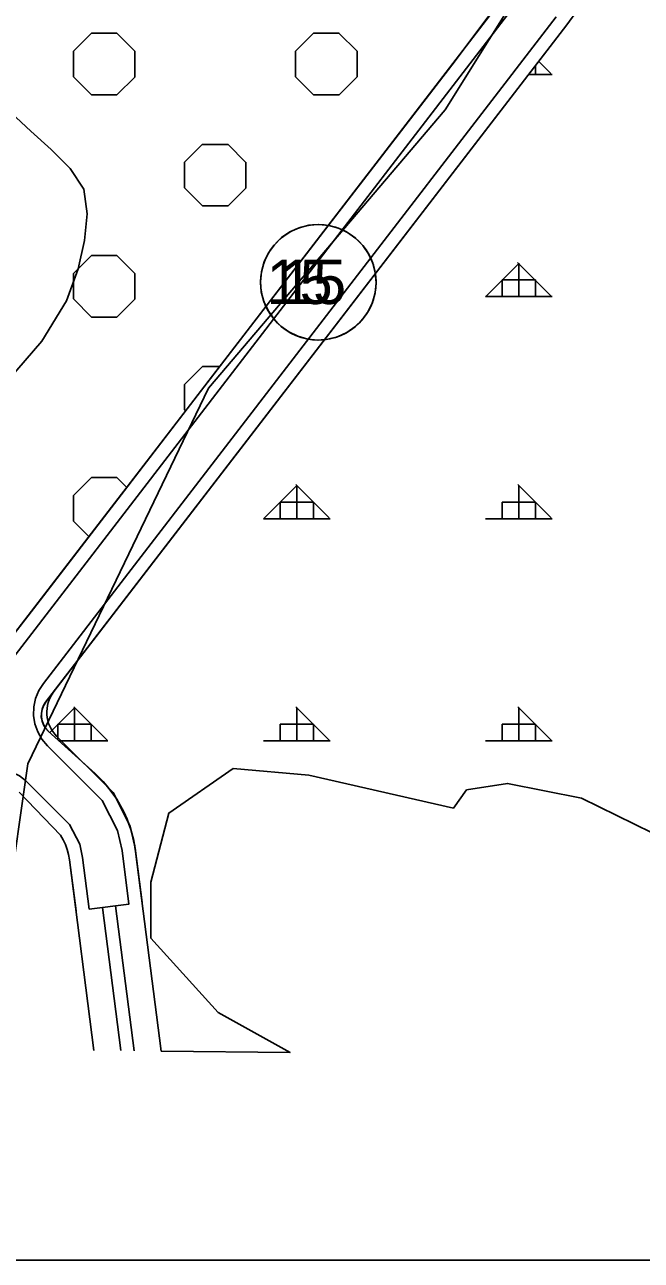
# Model space of a CAD drawing. Extents: x 410727 to 412947, y 4463506 to 4466382.
# Drawn here: x 410893.4 to 411032.2, y 4463506.2 to 4463784.3 of the extents above; entities that cross this region are included whole.
import ezdxf

# ---------------------------------------------------------------- set-up
doc = ezdxf.new("R2010")
doc.units = 0
for name, color, linetype in [('ADAKENARI', 7, 'Continuous'), ('F_ADAKENARI', 7, 'Continuous'), ('KALDIRIM', 7, 'Continuous'), ('LJ_ÇERÇEVE', 7, 'Continuous'), ('PL_AYA_AGACLANDIRIL', 7, 'Continuous'), ('PL_AYA_ORMAN', 7, 'Continuous'), ('SM_BEYAZ', 7, 'Continuous'), ('SM_DAİRE', 7, 'Continuous'), ('sm_yol_beyaz', 7, 'Continuous'), ('sm_yol_genisligi', 7, 'Continuous'), ('SM_YOLGEN', 7, 'Continuous'), ('TR_AGACLANDIRILACAK', 7, 'Continuous'), ('TR_ORMAN', 7, 'Continuous'), ('Yerlesime_uygunluk_sınırı', 7, 'Continuous')]:
    doc.layers.add(name, color=color, linetype=linetype)

msp = doc.modelspace()

# ---------------------------------------------------------------- linework, layer by layer
at = {"layer": 'ADAKENARI'}
for p, q in [((410998.01, 4463786.26), (410888.18, 4463643.49)), ((410898.1, 4463631.77), (411015.41, 4463784.28)), ((410899.96, 4463634.19), (411015.41, 4463784.28)), ((410909.24, 4463615.7), (410898.67, 4463625.3)), ((410913.31, 4463611.43), (410900.62, 4463624.08)), ((410940.29, 4463616.85), (410925.86, 4463606.84)), ((410957.32, 4463615.37), (410940.29, 4463616.85)), ((410989.89, 4463607.95), (410957.32, 4463615.37)), ((410992.85, 4463612.03), (410989.89, 4463607.95)), ((411002.1, 4463613.51), (410992.85, 4463612.03)), ((411018.76, 4463610.18), (411002.1, 4463613.51)), ((410917.14, 4463603.89), (410913.31, 4463611.43)), ((411034.67, 4463602.39), (411018.76, 4463610.18)), ((410925.86, 4463606.84), (410921.79, 4463591.26)), ((410918.26, 4463598.9), (410917.14, 4463603.89)), ((410919.82, 4463586.73), (410918.26, 4463598.9)), ((410924.1, 4463553.24), (410918.35, 4463598.21)), ((410903.47, 4463596.3), (410904.94, 4463584.83)), ((410921.79, 4463591.26), (410921.79, 4463578.65)), ((410921.79, 4463578.65), (410936.96, 4463561.96)), ((410921.79, 4463578.65), (410936.96, 4463561.96)), ((410936.96, 4463561.96), (410953.14, 4463552.9))]:
    msp.add_line(p, q, dxfattribs=at)
for centre, radius, start, end in [((410906.03, 4463629.51), 7.67, 142.4314, 225.1023), ((410901.9, 4463628.85), 4.79, 142.4314, 227.7263), ((410901.9, 4463628.85), 4.79, 142.4314, 227.7263), ((410890.04, 4463594.59), 28.53, 7.289, 47.7263), ((410890.04, 4463594.59), 28.53, 7.289, 47.7263)]:
    msp.add_arc(centre, radius, start, end, dxfattribs=at)
at = {"layer": 'F_ADAKENARI'}
for p, q in [((410898.1, 4463631.77), (411015.41, 4463784.28)), ((410997.92, 4463786.32), (410989.51, 4463775.21)), ((410989.51, 4463775.21), (410935.69, 4463705.24)), ((410935.69, 4463705.24), (410915.86, 4463679.46)), ((410915.86, 4463679.46), (410895.37, 4463652.83)), ((410895.37, 4463652.83), (410888.19, 4463643.49)), ((410898.1, 4463631.77), (410897.62, 4463631.02)), ((410897.13, 4463629.32), (410897.12, 4463628.43)), ((410897.12, 4463628.43), (410897.29, 4463627.55)), ((410897.3, 4463630.19), (410897.13, 4463629.32)), ((410897.62, 4463631.02), (410897.3, 4463630.19)), ((410897.29, 4463627.55), (410897.61, 4463626.72)), ((410897.61, 4463626.72), (410898.07, 4463625.96)), ((410898.07, 4463625.96), (410898.67, 4463625.3)), ((410909.24, 4463615.7), (410898.67, 4463625.3)), ((410911.02, 4463613.93), (410909.24, 4463615.7)), ((410912.65, 4463612), (410911.02, 4463613.93)), ((410914.09, 4463609.94), (410912.65, 4463612)), ((410901.45, 4463601.87), (410892.1, 4463611.52)), ((410915.35, 4463607.77), (410914.09, 4463609.94)), ((410916.42, 4463605.48), (410915.35, 4463607.77)), ((410917.27, 4463603.12), (410916.42, 4463605.48)), ((410902.05, 4463600.84), (410901.45, 4463601.87)), ((410902.55, 4463599.76), (410902.05, 4463600.84)), ((410917.92, 4463600.69), (410917.27, 4463603.12)), ((410918.35, 4463598.21), (410917.92, 4463600.69)), ((410902.96, 4463598.63), (410902.55, 4463599.76)), ((410903.27, 4463597.48), (410902.96, 4463598.63)), ((410924.1, 4463553.24), (410918.35, 4463598.21)), ((410903.47, 4463596.3), (410903.27, 4463597.48)), ((410903.47, 4463596.3), (410908.95, 4463553.42))]:
    msp.add_line(p, q, dxfattribs=at)
at = {"layer": 'KALDIRIM'}
for p, q in [((410915.01, 4463553.35), (410910.89, 4463585.59)), ((410918.04, 4463553.31), (410913.86, 4463585.97))]:
    msp.add_line(p, q, dxfattribs=at)
for points in [[(410869.51, 4463620.34), (410870.81, 4463620.5), (410872.09, 4463620.82), (410873.32, 4463621.3), (410874.48, 4463621.92), (410875.55, 4463622.67), (410876.53, 4463623.55), (410877.4, 4463624.54), (411005.8, 4463791.46)], [(411013.01, 4463786.08), (410897.58, 4463636.01), (410896.55, 4463634.39), (410895.83, 4463632.61), (410895.43, 4463630.73), (410895.39, 4463628.81), (410895.69, 4463626.91), (410896.32, 4463625.1), (410897.27, 4463623.43), (410898.5, 4463621.95), (410910.85, 4463609.64), (410914.29, 4463602.87), (410915.3, 4463598.38), (410916.84, 4463586.35), (410907.91, 4463585.21), (410906.43, 4463596.82), (410905.76, 4463599.8), (410903.48, 4463604.29), (410893.55, 4463614.18)], [(410893.55, 4463614.18), (410892.2, 4463615.24), (410890.63, 4463615.94), (410888.94, 4463616.25), (410887.23, 4463616.15), (410885.59, 4463615.63), (410884.12, 4463614.75), (410882.91, 4463613.53), (410882.02, 4463612.06), (410855.88, 4463554.04)]]:
    msp.add_lwpolyline(points, dxfattribs=at)
at = {"layer": 'LJ_ÇERÇEVE'}
msp.add_lwpolyline([(410732.32, 4466381.6), (412946.74, 4466381.6), (412946.74, 4463506.16), (410732.32, 4463506.16)], close=True, dxfattribs=at)
at = {"layer": 'PL_AYA_AGACLANDIRIL'}
msp.add_lwpolyline([(410768.78, 4463916.77), (410766.18, 4463697.48), (410777.91, 4463692.29), (410788.9, 4463688.62), (410805.39, 4463682.42), (410820.27, 4463677.15), (410829.43, 4463674.39), (410842.25, 4463668.64), (410849.8, 4463665.2), (410858.96, 4463661.3), (410863.08, 4463657.85), (410871.02, 4463653.05), (410882.92, 4463646.63), (410888.18, 4463643.49), (410998.01, 4463786.26)], dxfattribs=at)
at = {"layer": 'PL_AYA_ORMAN'}
for points in [[(411018.08, 4463787.85), (411015.41, 4463784.28), (410898.1, 4463631.77), (410897.62, 4463631.02), (410897.3, 4463630.19), (410897.13, 4463629.32), (410897.12, 4463628.43), (410897.29, 4463627.55), (410897.61, 4463626.72), (410898.07, 4463625.96), (410898.67, 4463625.3), (410909.24, 4463615.7), (410911.02, 4463613.93), (410912.65, 4463612), (410914.09, 4463609.94), (410915.35, 4463607.77), (410916.42, 4463605.48), (410917.27, 4463603.12), (410917.92, 4463600.69), (410918.35, 4463598.21), (410924.1, 4463553.24)], [(410924.1, 4463553.24), (410953.14, 4463552.9), (410936.96, 4463561.96), (410921.79, 4463578.65), (410921.79, 4463591.26), (410925.86, 4463606.84), (410940.29, 4463616.85), (410957.32, 4463615.37), (410989.89, 4463607.95), (410992.85, 4463612.03), (411002.1, 4463613.51), (411018.76, 4463610.18), (411034.67, 4463602.39), (411057.99, 4463584.96), (411067.25, 4463601.65), (411078.72, 4463599.05), (411105, 4463582.73), (411130.91, 4463564.19), (411151.28, 4463550.58), (411512.89, 4463546.35)]]:
    msp.add_lwpolyline(points, dxfattribs=at)
at = {"layer": 'SM_BEYAZ'}
for start, end in [(0, 180), (180, 0)]:
    msp.add_arc((410959.48, 4463726.31), 13, start, end, dxfattribs=at)
at = {"layer": 'SM_DAİRE'}
msp.add_lwpolyline([(410972.48, 4463726.18), (410972.26, 4463723.93), (410971.65, 4463721.74), (410970.67, 4463719.7), (410969.35, 4463717.86), (410967.74, 4463716.27), (410965.87, 4463714.99), (410963.8, 4463714.05), (410961.61, 4463713.48), (410959.35, 4463713.31), (410957.09, 4463713.53), (410954.91, 4463714.14), (410952.87, 4463715.12), (410951.02, 4463716.43), (410949.44, 4463718.05), (410948.16, 4463719.92), (410947.22, 4463721.98), (410946.65, 4463724.18), (410946.48, 4463726.44), (410946.7, 4463728.69), (410947.31, 4463730.88), (410948.28, 4463732.92), (410949.6, 4463734.76), (410951.22, 4463736.35), (410953.09, 4463737.63), (410955.15, 4463738.57), (410957.35, 4463739.13), (410959.61, 4463739.31), (410961.86, 4463739.09), (410964.04, 4463738.48), (410966.09, 4463737.5), (410967.93, 4463736.19), (410969.52, 4463734.57), (410970.8, 4463732.7), (410971.74, 4463730.63), (410972.3, 4463728.44), (410972.48, 4463726.18)], dxfattribs=at)
msp.add_lwpolyline([(410972.48, 4463726.18), (410972.26, 4463723.93), (410971.65, 4463721.74), (410970.67, 4463719.7), (410969.35, 4463717.86), (410967.74, 4463716.27), (410965.87, 4463714.99), (410963.8, 4463714.05), (410961.61, 4463713.48), (410959.35, 4463713.31), (410957.09, 4463713.53), (410954.91, 4463714.14), (410952.87, 4463715.12), (410951.02, 4463716.43), (410949.44, 4463718.05), (410948.16, 4463719.92), (410947.22, 4463721.98), (410946.65, 4463724.18), (410946.48, 4463726.44), (410946.7, 4463728.69), (410947.31, 4463730.88), (410948.28, 4463732.92), (410949.6, 4463734.76), (410951.22, 4463736.35), (410953.09, 4463737.63), (410955.15, 4463738.57), (410957.35, 4463739.13), (410959.61, 4463739.31), (410961.86, 4463739.09), (410964.04, 4463738.48), (410966.09, 4463737.5), (410967.93, 4463736.19), (410969.52, 4463734.57), (410970.8, 4463732.7), (410971.74, 4463730.63), (410972.3, 4463728.44), (410972.48, 4463726.18)], dxfattribs=at)
at = {"layer": 'sm_yol_beyaz'}
msp.add_lwpolyline([(410972.48, 4463726.18), (410972.3, 4463728.44), (410971.74, 4463730.63), (410970.8, 4463732.7), (410969.52, 4463734.57), (410967.93, 4463736.19), (410966.09, 4463737.5), (410964.04, 4463738.48), (410961.86, 4463739.09), (410959.61, 4463739.31), (410957.35, 4463739.13), (410955.15, 4463738.57), (410953.09, 4463737.63), (410951.22, 4463736.35), (410949.6, 4463734.76), (410948.28, 4463732.92), (410947.31, 4463730.88), (410946.7, 4463728.69), (410946.48, 4463726.44), (410946.65, 4463724.18), (410947.22, 4463721.98), (410948.16, 4463719.92), (410949.44, 4463718.05), (410951.02, 4463716.43), (410952.87, 4463715.12), (410954.91, 4463714.14), (410957.09, 4463713.53), (410959.35, 4463713.31), (410961.61, 4463713.48), (410963.8, 4463714.05), (410965.87, 4463714.99), (410967.74, 4463716.27), (410969.35, 4463717.86), (410970.67, 4463719.7), (410971.65, 4463721.74), (410972.26, 4463723.93), (410972.48, 4463726.18)], dxfattribs=at)
at = {"layer": 'sm_yol_genisligi'}
msp.add_circle((410959.48, 4463726.31), 13, dxfattribs=at)
at = {"layer": 'TR_AGACLANDIRILACAK'}
for p, q in [((410904.34, 4463778.31), (410908.4, 4463782.37)), ((410908.42, 4463782.35), (410914.16, 4463782.35)), ((410918.2, 4463778.3), (410914.14, 4463782.36)), ((410954.34, 4463778.31), (410958.4, 4463782.37)), ((410958.42, 4463782.35), (410964.16, 4463782.35)), ((410968.2, 4463778.3), (410964.14, 4463782.36)), ((410904.34, 4463772.57), (410904.34, 4463778.31)), ((410918.2, 4463772.57), (410918.2, 4463778.31)), ((410954.34, 4463772.57), (410954.34, 4463778.31)), ((410968.2, 4463772.57), (410968.2, 4463778.31)), ((410908.42, 4463768.49), (410904.36, 4463772.55)), ((410914.16, 4463768.49), (410918.22, 4463772.55)), ((410958.42, 4463768.49), (410954.36, 4463772.55)), ((410964.16, 4463768.49), (410968.22, 4463772.55)), ((410908.42, 4463768.49), (410914.16, 4463768.49)), ((410958.42, 4463768.49), (410964.16, 4463768.49)), ((410929.34, 4463753.31), (410933.4, 4463757.37)), ((410933.42, 4463757.35), (410939.16, 4463757.35)), ((410943.2, 4463753.3), (410939.14, 4463757.36)), ((410929.34, 4463747.57), (410929.34, 4463753.31)), ((410943.2, 4463747.57), (410943.2, 4463753.31)), ((410933.42, 4463743.49), (410929.36, 4463747.55)), ((410939.16, 4463743.49), (410943.22, 4463747.55)), ((410933.42, 4463743.49), (410939.16, 4463743.49)), ((410904.34, 4463728.31), (410908.4, 4463732.37)), ((410908.42, 4463732.35), (410914.16, 4463732.35)), ((410918.2, 4463728.3), (410914.14, 4463732.36)), ((410904.34, 4463722.57), (410904.34, 4463728.31)), ((410918.2, 4463722.57), (410918.2, 4463728.31)), ((410908.42, 4463718.49), (410904.36, 4463722.55)), ((410914.16, 4463718.49), (410918.22, 4463722.55)), ((410908.42, 4463718.49), (410914.16, 4463718.49)), ((410929.34, 4463703.31), (410933.4, 4463707.37)), ((410929.34, 4463703.31), (410933.4, 4463707.37)), ((410933.42, 4463707.35), (410937.31, 4463707.35)), ((410933.42, 4463707.35), (410937.31, 4463707.35)), ((410929.34, 4463697.57), (410929.34, 4463703.31)), ((410929.34, 4463697.57), (410929.34, 4463703.31)), ((410929.59, 4463697.32), (410929.36, 4463697.55)), ((410929.59, 4463697.32), (410929.36, 4463697.55)), ((410904.34, 4463678.31), (410908.4, 4463682.37)), ((410908.42, 4463682.35), (410914.16, 4463682.35)), ((410908.42, 4463682.35), (410914.16, 4463682.35)), ((410916.37, 4463680.13), (410914.14, 4463682.36)), ((410916.37, 4463680.13), (410914.14, 4463682.36)), ((410904.34, 4463672.57), (410904.34, 4463678.31)), ((410904.34, 4463672.57), (410904.34, 4463678.31)), ((410907.85, 4463669.05), (410904.36, 4463672.55)), ((410907.85, 4463669.05), (410904.36, 4463672.55))]:
    msp.add_line(p, q, dxfattribs=at)
at = {"layer": 'TR_ORMAN'}
for p, q in [((411011.82, 4463773.31), (411009.08, 4463776.05)), ((411011.82, 4463773.31), (411009.08, 4463776.05)), ((411006.8, 4463773.09), (411012.12, 4463773.09)), ((411006.8, 4463773.09), (411012.12, 4463773.09)), ((411008.37, 4463773.09), (411008.37, 4463775.13)), ((411008.37, 4463773.09), (411008.37, 4463775.13)), ((410997.12, 4463723.04), (411004.62, 4463730.54)), ((410997.12, 4463723.04), (411004.62, 4463730.54)), ((411011.85, 4463723.28), (411004.36, 4463730.78)), ((411011.85, 4463723.28), (411004.36, 4463730.78)), ((411004.62, 4463723.09), (411004.62, 4463730.59)), ((411004.62, 4463723.09), (411004.62, 4463730.59)), ((411000.87, 4463723.09), (411000.87, 4463726.84)), ((411000.87, 4463726.84), (411008.37, 4463726.84)), ((411000.87, 4463723.09), (411000.87, 4463726.84)), ((411000.87, 4463726.84), (411008.37, 4463726.84)), ((411008.37, 4463723.09), (411008.37, 4463726.84)), ((411008.37, 4463723.09), (411008.37, 4463726.84)), ((410997.12, 4463723.09), (411012.12, 4463723.09)), ((410997.12, 4463723.09), (411012.12, 4463723.09)), ((410947.12, 4463673.04), (410954.62, 4463680.54)), ((410961.89, 4463673.26), (410954.4, 4463680.76)), ((410954.62, 4463673.09), (410954.62, 4463680.59)), ((411011.89, 4463673.26), (411004.39, 4463680.76)), ((411004.62, 4463673.09), (411004.62, 4463680.59)), ((410950.87, 4463673.09), (410950.87, 4463676.84)), ((410950.87, 4463676.84), (410958.37, 4463676.84)), ((410958.37, 4463673.09), (410958.37, 4463676.84)), ((411000.87, 4463673.09), (411000.87, 4463676.84)), ((411000.87, 4463676.84), (411008.37, 4463676.84)), ((411008.37, 4463673.09), (411008.37, 4463676.84)), ((410947.12, 4463673.09), (410962.12, 4463673.09)), ((410997.12, 4463673.09), (411012.12, 4463673.09)), ((410899.05, 4463624.97), (410904.62, 4463630.54)), ((410911.93, 4463623.24), (410904.43, 4463630.73)), ((410904.62, 4463623.09), (410904.62, 4463630.59)), ((410961.93, 4463623.24), (410954.43, 4463630.73)), ((410954.62, 4463623.09), (410954.62, 4463630.59)), ((411011.92, 4463623.24), (411004.42, 4463630.73)), ((411004.62, 4463623.09), (411004.62, 4463630.59)), ((410900.87, 4463623.3), (410900.87, 4463626.84)), ((410900.87, 4463626.84), (410908.37, 4463626.84)), ((410908.37, 4463623.09), (410908.37, 4463626.84)), ((410950.87, 4463623.09), (410950.87, 4463626.84)), ((410950.87, 4463626.84), (410958.37, 4463626.84)), ((410958.37, 4463623.09), (410958.37, 4463626.84)), ((411000.87, 4463623.09), (411000.87, 4463626.84)), ((411000.87, 4463626.84), (411008.37, 4463626.84)), ((411008.37, 4463623.09), (411008.37, 4463626.84)), ((410901.11, 4463623.09), (410912.12, 4463623.09)), ((410947.12, 4463623.09), (410962.12, 4463623.09)), ((410997.12, 4463623.09), (411012.12, 4463623.09))]:
    msp.add_line(p, q, dxfattribs=at)
at = {"layer": 'Yerlesime_uygunluk_sınırı'}
for points in [[(410884.89, 4463553.7), (410894.05, 4463617.91), (410934.73, 4463702.48), (410988.03, 4463765.12), (411028.04, 4463829.11), (411029.72, 4463859.7), (410999.92, 4463882.1), (410947.76, 4463889.1), (410882.25, 4463887.07), (410838.73, 4463905.99), (410831.65, 4463926.92), (410768.92, 4463928.35)], [(410886.36, 4463700.55), (410897.23, 4463713.07), (410902.79, 4463722.14), (410905.43, 4463729.31), (410906.86, 4463735.73), (410907.45, 4463741.75), (410906.66, 4463747.25), (410903.59, 4463751.94), (410899.32, 4463756.2), (410894.73, 4463760.33), (410890.36, 4463764.47)]]:
    msp.add_lwpolyline(points, dxfattribs=at)

# ---------------------------------------------------------------- texts
at = {"layer": 'sm_yol_genisligi'}
msp.add_text('15', height=10, dxfattribs=at).set_placement((410947.84, 4463721.41))
at = {"layer": 'SM_YOLGEN'}
msp.add_text('15', height=10, dxfattribs=at).set_placement((410950.87, 4463721.41))
msp.add_text('15', height=10, dxfattribs=at).set_placement((410950.87, 4463721.41))

doc.saveas('drawing.dxf')
